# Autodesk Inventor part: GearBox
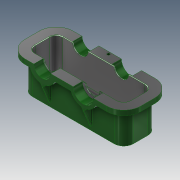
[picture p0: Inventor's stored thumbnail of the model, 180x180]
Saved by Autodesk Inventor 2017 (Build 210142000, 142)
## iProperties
Created: 2016-10
Part Number: GearBox
Material: Generic
Document SubType Name: Modeling
Designer: Drago Šandor
Density: 1 g/cm^3
Appearance: Smooth - Dark Forest Green
Author: Drago Šandor
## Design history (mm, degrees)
sketch "Sketch1"
  geometry: L1 (0, -147)-(0, 147) reference; L2 (-49, 0)-(49, 0) reference; L3 (35, 105)-(-35, 105); L4 (-35, 105)-(-35, -105); L5 (-35, -105)-(35, -105); L6 (35, -105)-(35, 105); 3 further points
  constraints: 8 end point, 2 midpoint, 2 parallel, 2 point on line, 1 horizontal, 1 perpendicular
  dimensions: "d0" = 70 distance of L4.end L5.end; "d1" = 210 distance of L5.end L3.start
extrude "Extrusion1" new body sketch "Sketch1" distance "d2" = 90; taper "d3" = 0 deg
fillet "Fillet1" dims "d4" = 20
shell "Shell1" dims "d5" = 6
fillet "Fillet2" dims "d6" = 20
sketch "Sketch2"
  geometry: L1 (-15, -105)-(15, -105) reference; L2 (-35, 85)-(-35, -85) reference; L3 (15, 105)-(-15, 105) reference; L4 (35, -85)-(35, 85) reference; L5 (-15, -127)-(15, -127); L6 (57, -85)-(57, 85); L7 (15, 127)-(-15, 127); L8 (-57, 85)-(-57, -85); A1 r 20 centre (-15, -85) between (-35, -85) and (-15, -105) reference; A2 r 20 centre (-15, 85) between (-15, 105) and (-35, 85) reference; A3 r 20 centre (15, 85) between (35, 85) and (15, 105) reference; A4 r 20 centre (15, -85) between (15, -105) and (35, -85) reference; A5 r 42 centre (-15, -85) between (-57, -85) and (-15, -127); A6 r 42 centre (15, -85) between (15, -127) and (57, -85); A7 r 42 centre (15, 85) between (57, 85) and (15, 127); A8 r 42 centre (-15, 85) between (-15, 127) and (-57, 85); 1 further point
  constraints: 8 end point, 8 point on circle, 4 centre point
  dimensions: "d7" = 22 distance between parallel lines of L2 L8
extrude "Extrusion2" join sketch "Sketch2" distance "d8" = 10; taper "d9" = 0 deg
sketch "Sketch3"
  geometry: L1 (35, -85)-(35, 85) reference; L2 (-15, -105)-(15, -105) reference; L3 (-35, 85)-(-35, -85) reference; L4 (15, 105)-(-15, 105) reference; L5 (15, 120)-(-15, 120); L6 (-50, 85)-(-50, -85); L7 (-15, -120)-(15, -120); L8 (50, -85)-(50, 85); A1 r 20 centre (15, 85) between (35, 85) and (15, 105) reference; A2 r 20 centre (15, -85) between (15, -105) and (35, -85) reference; A3 r 20 centre (-15, -85) between (-35, -85) and (-15, -105) reference; A4 r 20 centre (-15, 85) between (-15, 105) and (-35, 85) reference; A5 r 35 centre (15, 85) between (50, 85) and (15, 120); A6 r 35 centre (-15, 85) between (-15, 120) and (-50, 85); A7 r 35 centre (-15, -85) between (-50, -85) and (-15, -120); A8 r 35 centre (15, -85) between (15, -120) and (50, -85); 1 further point
  constraints: 8 end point, 8 point on circle, 4 centre point
  dimensions: "d10" = 15 distance between parallel lines of L1 L8
extrude "Extrusion3" join sketch "Sketch3" distance "d11" = 10; taper "d12" = 0 deg
sketch "Sketch4"
  geometry: L1 (30, 0)-(0, 0) reference; L2 (-12, 0)-(42, 0); L3 (42, 0)-(42, 5); L4 (42, 5)-(-12, 5); L5 (-12, 5)-(-12, 0); L6 (-42, 0)-(-42, 10) reference; L7 (72, 0)-(72, 10) reference; 1 further point
  constraints: 8 end point, 2 parallel, 1 horizontal, 1 perpendicular, 1 point on line
  dimensions: "d13" = 5 distance of L2.end L3.end; "d14" = 30 distance between parallel lines of L5 L6; "d15" = 30 distance between parallel lines of L7 L3
extrude "Extrusion4" cut sketch "Sketch4" stored distance "d16" = 10; taper "d17" = 0 deg
fillet "Fillet3" dims "d18" = 5
fillet "Fillet4" dims "d19" = 5
chamfer "Chamfer1" distance "d20" = 1; stored, may be unused: second distance "d21" = 2, angle "d22" = 45 deg
sketch "Sketch5"
  geometry: L1 (0, 0)-(170, 0) reference; L2 (184, -64)-(184, -1) reference; L3 (205, 0)-(170, 0) reference; L4 (170, -1)-(184, -1) reference; L5 (0, 0)-(170, 0) reference; L6 (21.5, 0)-(76.5, 0); L7 (106.5, 0)-(161.5, 0); A1 r 27.5 centre (49, 0) between (21.5, 0) and (76.5, 0); A2 r 27.5 centre (134, 0) between (106.5, 0) and (161.5, 0); 2 further points
  constraints: 6 point on line, 4 end point, 4 point on circle, 2 centre point, 2 collinear, 1 coincident
  dimensions: "d23" = 55 diameter of A1; "d24" = 55 diameter of A2; "d25" = 50 horizontal distance of A2.centre point (184, -1); "d26" = 85 distance of A1.centre A2.centre
extrude "Extrusion5" join sketch "Sketch5" stored distance "d27" = 10; taper "d28" = 0 deg
sketch "Sketch6"
  geometry: C1 r 17.5 at (49, 0); C2 r 18.5 at (134, 0); A1 r 27.5 centre (49, 0) between (23.383, -10) and (74.617, -10) reference; A2 r 27.5 centre (134, 0) between (108.383, -10) and (159.617, -10) reference; 1 further point
  constraints: 2 centre point, 2 coincident
  dimensions: "d29" = 35 diameter of C1; "d30" = 37 diameter of C2
extrude "Extrusion6" cut sketch "Sketch6" distance "d31" = 19; taper "d32" = 0 deg
sketch "Sketch7"
  geometry: L1 (34, 0)-(64, 0); L2 (0, 0)-(170, 0) reference; L3 (118, 0)-(150, 0); A1 r 17.5 centre (49, 0) between (31.5, 0) and (66.5, 0) reference; A2 r 18.5 centre (134, 0) between (115.5, 0) and (152.5, 0) reference; A3 r 15 centre (49, 0) between (34, 0) and (64, 0); A4 r 16 centre (134, 0) between (118, 0) and (150, 0); 1 further point
  constraints: 4 end point, 4 point on circle, 2 centre point, 2 collinear
  dimensions: "d33" = 2.5 radial gap between concentric circles of A1 A3; "d34" = 2.5 radial gap between concentric circles of A2 A4
extrude "Extrusion7" cut sketch "Sketch7" stored distance "d35" = 19; taper "d36" = 0 deg
workaxis "Work Axis1"
workaxis "Work Axis2"
workplane "Work Plane1"
workplane "Work Plane2"
sketch "Sketch8"
  geometry: L1 (0, 10)-(0, 27.5) reference; L2 (0, 27.5)-(0, 32.5); L3 (0, 27.5)-(15, 27.5) reference; L4 (15, 75)-(15, 10) reference; L5 (0, 32.5)-(15, 67.5); L6 (15, 27.5)-(15, 67.5); L7 (15, 10)-(15, 75) reference; L8 (15, 27.5)-(0, 27.5); 1 further point
  constraints: 8 end point, 2 collinear, 1 point on line, 1 vertical
  dimensions: "d39" = 5 distance of L1.end L2.end; "d40" = 35 vertical distance of L5.end L2.end
feature "Rib1" sketch "Sketch8" dims "d41" = 1, "d42" = 5, "d43" = 0, "d44" = 0, "d45" = 1, "d46" = 1
sketch "Sketch10"
  geometry: L1 (0, 27.5)-(15, 27.5) reference; L2 (15, 10)-(15, 75) reference; L3 (0, 27.5)-(0, 32.5); L4 (0, 32.5)-(15, 67.5); 1 further point
  constraints: 4 end point, 1 point on line, 1 vertical
  dimensions: "d47" = 5 distance of L1.start L3.end; "d48" = 35 vertical distance of L4.end L3.end
feature "Rib2" sketch "Sketch10" dims "d49" = 1, "d50" = 5, "d51" = 0, "d52" = 0, "d53" = 1, "d54" = 1
fillet "Fillet5" dims "d55" = 2
workplane "Work Plane3"
mirror "Mirror1"
fillet "Fillet6" dims "d56" = 5
fillet "Fillet7" dims "d57" = 2
sketch "Sketch11"
  geometry: L1 (150, 10)-(170, 10) reference; L2 (152.5, 10)-(151.5, 10); L3 (116.5, 10)-(115.5, 10); A1 r 18.5 centre (134, 10) between (115.5, 10) and (152.5, 10) reference; A2 r 17.5 centre (134, 10) between (116.5, 10) and (151.5, 10); A3 r 18.5 centre (134, 10) between (115.5, 10) and (152.5, 10); 2 further points
  constraints: 4 end point, 4 point on circle, 2 centre point, 2 coincident
  dimensions: "d58" = 35 diameter of A2
extrude "Extrusion8" join sketch "Sketch11" stored distance "d59" = 10; taper "d60" = 0 deg
sketch "Sketch12"
  geometry: C1 r 21 at (49, 10); A1 r 17.5 centre (49, 10) between (31.5, 10) and (66.5, 10) reference; 1 further point
  constraints: 1 centre point, 1 coincident
  dimensions: "d61" = 42 diameter of C1
extrude "Extrusion9" cut sketch "Sketch12" stored distance "d62" = 10; taper "d63" = 0 deg
mirror "Mirror2"
sketch "Sketch13"
  geometry: L1 (57, -85)-(57, 85) reference; L2 (40, 23.383)-(50, 23.383) reference; L3 (35.162, -36.5)-(50, -36.5) reference; L4 (50, -10.383)-(40, -10.383) reference; 2 further points
  dimensions: "d64" = 12 distance from line of L1 point (45, 6.617); "d68" = 17 distance from line of L4 point (45, 6.617)
hole "Hole1" sketch "Sketch13" at (45, 6.617) diameter "d69" = 5; stored, may be unused: countersink angle "d73" = 90 deg, drill point angle "d75" = 118 deg; dims "d70" = 6, "d71" = 4, "d72" = 2, "d74" = 8
sketch "Sketch14"
  geometry: L1 (52, 10)-(54.5, 10) reference; L2 (53.5, 10)-(54.5, 10); L3 (18.5, 10)-(17.5, 10); L4 (0, 10)-(20, 10) reference; A1 r 18.5 centre (36, 10) between (17.5, 10) and (54.5, 10) reference; A2 r 18.5 centre (36, 10) between (17.5, 10) and (54.5, 10); A3 r 17.5 centre (36, 10) between (18.5, 10) and (53.5, 10) reference; A4 r 17.5 centre (36, 10) between (53.5, 10) and (53.5, 10); 1 further point
  constraints: 4 end point, 4 point on circle, 2 centre point, 2 coincident, 2 collinear
  dimensions: "d76" = 17.5 radius of A4 (derived)
extrude "Extrusion10" join sketch "Sketch14" stored distance "d77" = 10; taper "d78" = 0 deg
sketch "Sketch15"
  geometry: L1 (-49.526, 15)-(221.391, 15); L2 (221.391, 15)-(221.391, -7.273); L3 (221.391, -7.273)-(-49.526, -7.273); L4 (-49.526, -7.273)-(-49.526, 15); 1 further point
  constraints: 8 end point, 2 parallel, 1 horizontal, 1 perpendicular
extrude "Extrusion11" cut sketch "Sketch15" stored distance "d79" = 10; taper "d80" = 0 deg
body "Solid1"
other parameters: "d37" = 0, "d38" = 0
